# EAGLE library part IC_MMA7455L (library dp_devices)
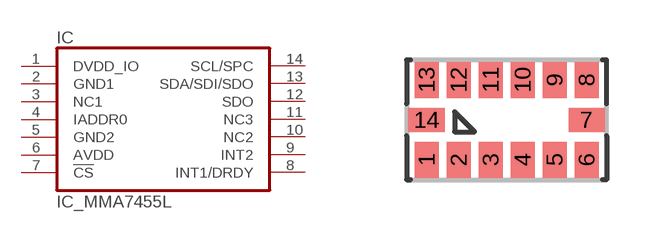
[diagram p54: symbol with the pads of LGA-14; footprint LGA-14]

Designator prefix IC

## IC_MMA7455L  [LGA-14]
1  DVDD_IO  pwr
2  GND1  pwr
3  NC1  nc
4  IADDR0  in
5  GND2  pwr
6  AVDD  pwr
7  !CS  in
8  INT1/DRDY  out
9  INT2  out
10  NC2  nc
11  NC3  nc
12  SDO  out
13  SDA/SDI/SDO
14  SCL/SPC  in

## Footprint LGA-14 (pad centres in mm)
smd 0.6 x 0.9: 1 -2,-1; 2 -1.2,-1; 3 -0.4,-1; 4 0.4,-1; 5 1.2,-1; 6 2,-1; 8 2,1; 9 1.2,1; 10 0.4,1; 11 -0.4,1; 12 -1.2,1; 13 -2,1
smd 0.9 x 0.6: 7 2,0; 14 -2,0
